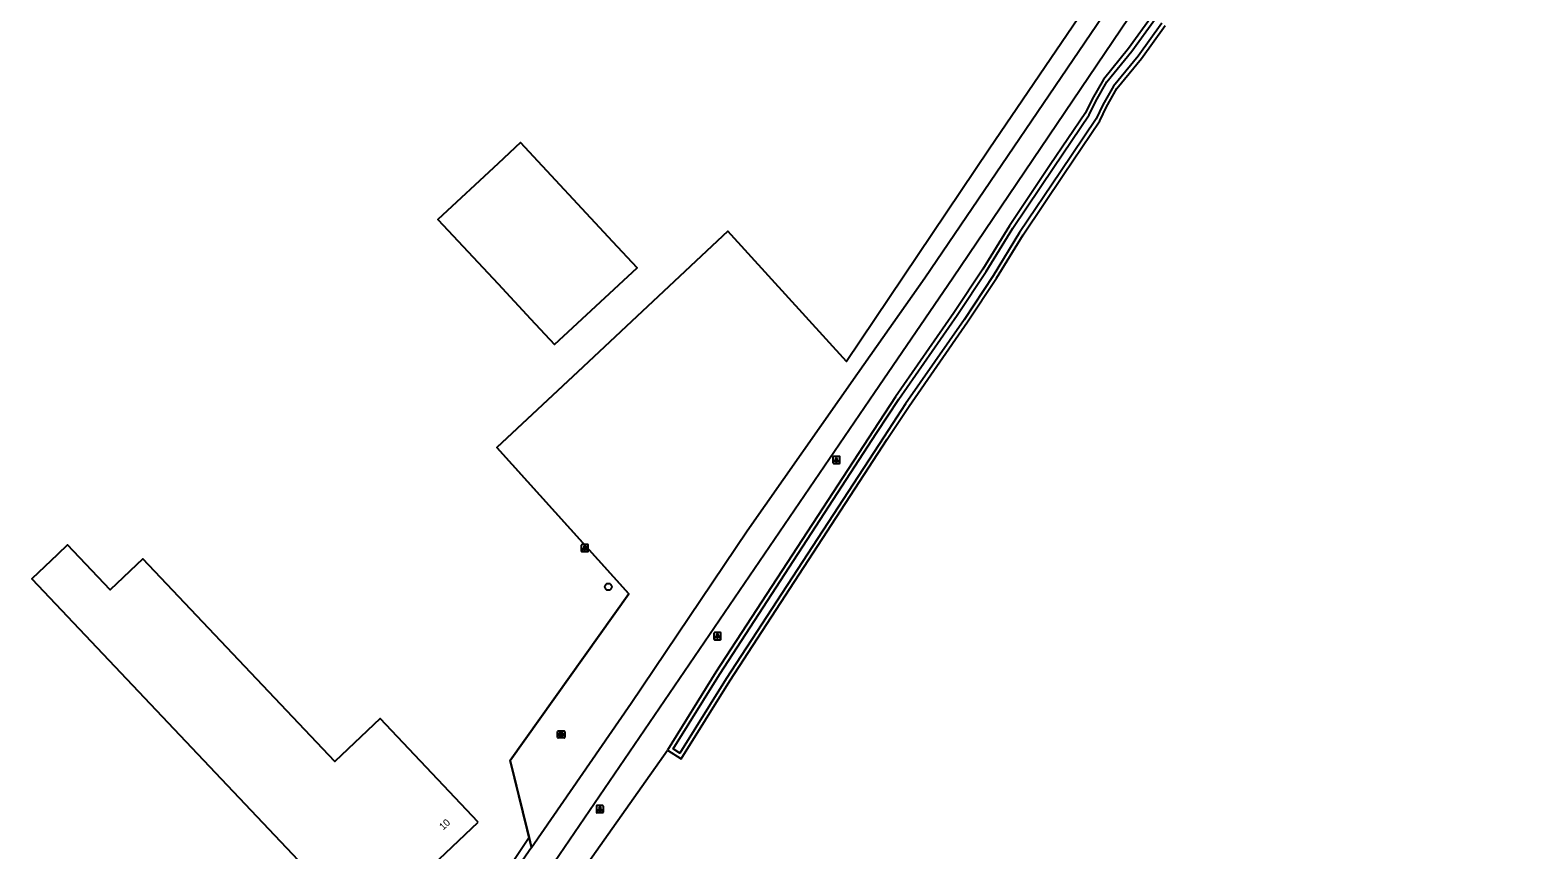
# Model space of a CAD drawing. Extents: x 158132 to 159658, y 385257 to 387209.
# Drawn here: x 158933.8 to 159147, y 385752.7 to 385868.6 of the extents above; entities that cross this region are included whole.
import ezdxf

# ---------------------------------------------------------------- set-up
doc = ezdxf.new("R2010")
doc.units = 0
for name, color, linetype in [('IMGEO_Berm_groen', 7, 'Continuous'), ('IMGEO_Boom', 7, 'Continuous'), ('IMGEO_Gemengd_bos', 7, 'Continuous'), ('IMGEO_Hek', 7, 'Continuous'), ('IMGEO_Lichtpunt', 7, 'Continuous'), ('IMGEO_Pand', 7, 'Continuous'), ('IMGEO_Pand_nummerreeks', 7, 'Continuous'), ('IMGEO_Rijbaan_lokaal_gesloten', 7, 'Continuous'), ('IMGEO_Rioolput', 7, 'Continuous'), ('IMGEO_Waterloop', 7, 'Continuous')]:
    doc.layers.add(name, color=color, linetype=linetype)

msp = doc.modelspace()

# ---------------------------------------------------------------- linework, layer by layer
at = {"layer": 'IMGEO_Berm_groen'}
for points in [[(159092.49, 385870.57), (159089.15, 385865.96), (159085.62, 385861.61), (159084.01, 385858.81), (159083.09, 385856.9), (159078.1, 385849.51), (159072.31, 385840.89), (159068.55, 385834.77), (159064.47, 385828.62), (159056.21, 385816.73), (159053.11, 385812.01), (159030.82, 385777.84), (159023.96, 385766.81)], [(159265.28, 385343.7), (159132.55, 385500.97), (159107.6, 385530.31), (159026.33, 385627.91), (159001.16, 385658.64), (158979.01, 385685.68), (158978.13, 385686.75), (158977.84, 385687.14), (158977.57, 385687.54), (158977.31, 385687.95), (158977.22, 385688.1), (158977.12, 385688.27), (158977.03, 385688.43), (158976.49, 385689.52), (158976.05, 385690.66), (158975.73, 385691.84), (158975.51, 385693.04), (158975.4, 385694.25), (158975.4, 385695.47), (158975.51, 385696.69), (158975.74, 385697.89), (158976.08, 385699.06), (158976.35, 385699.45), (159023.96, 385766.81)], [(159004.39, 385754.5), (158972.66, 385706.93)], [(159004.39, 385754.5), (159004.75, 385753.06)]]:
    msp.add_lwpolyline(points, dxfattribs=at)
at = {"layer": 'IMGEO_Boom'}
msp.add_circle((159015.6, 385789.9), 0.489, dxfattribs=at)
at = {"layer": 'IMGEO_Gemengd_bos'}
for points in [[(158893.29, 385791.82), (158915.63, 385812.94), (158887.87, 385842.1), (158903.84, 385865.93), (158906.36, 385869.7), (158907.24, 385871.01), (158908.62, 385873.86), (158932.07, 385908.86), (158950.18, 385917.14), (158998.15, 385961.05), (159000, 385959.04), (159072.96, 385880.17), (159082.08, 385870.32), (159069.43, 385851.76), (159049.28, 385821.74), (159032.5, 385840.15), (159012.02, 385820.99), (158999.83, 385809.57), (159018.49, 385788.89), (159001.72, 385765.38), (159004.39, 385754.5)], [(159023.96, 385766.81), (159025.91, 385765.6), (159032.76, 385776.6), (159055.04, 385810.75), (159058.12, 385815.44), (159066.38, 385827.33), (159070.49, 385833.53), (159074.25, 385839.64), (159080.01, 385848.22), (159085.09, 385855.75), (159086.05, 385857.73), (159087.52, 385860.3), (159090.98, 385864.55), (159094.35, 385869.21)]]:
    msp.add_lwpolyline(points, dxfattribs=at)
at = {"layer": 'IMGEO_Hek'}
for points in [[(159072.96, 385880.17), (159082.08, 385870.32), (159069.43, 385851.76)], [(159069.43, 385851.76), (159049.28, 385821.74)], [(159049.28, 385821.74), (159032.5, 385840.15), (159012.02, 385820.99)], [(159004.75, 385753.06), (159001.72, 385765.38), (159018.49, 385788.89), (158999.83, 385809.57), (159012.02, 385820.99)]]:
    msp.add_lwpolyline(points, dxfattribs=at)
at = {"layer": 'IMGEO_Lichtpunt'}
for p, q in [((159047.35, 385808.23), (159047.35, 385807.43)), ((159047.35, 385808.23), (159047.35, 385807.43)), ((159048.25, 385808.33), (159047.44, 385808.33)), ((159048.25, 385808.33), (159047.44, 385808.33)), ((159048.34, 385807.43), (159048.34, 385808.23)), ((159048.34, 385807.43), (159048.34, 385808.23)), ((159047.44, 385807.33), (159048.25, 385807.33)), ((159047.44, 385807.33), (159048.25, 385807.33)), ((159011.77, 385795.77), (159011.77, 385794.97)), ((159011.77, 385795.77), (159011.77, 385794.97)), ((159012.67, 385795.87), (159011.87, 385795.87)), ((159012.67, 385795.87), (159011.87, 385795.87)), ((159012.77, 385794.97), (159012.77, 385795.77)), ((159012.77, 385794.97), (159012.77, 385795.77)), ((159011.87, 385794.87), (159012.67, 385794.87)), ((159011.87, 385794.87), (159012.67, 385794.87)), ((159030.53, 385783.33), (159030.53, 385782.53)), ((159030.53, 385783.33), (159030.53, 385782.53)), ((159031.43, 385783.43), (159030.63, 385783.43)), ((159031.43, 385783.43), (159030.63, 385783.43)), ((159030.63, 385782.43), (159031.43, 385782.43)), ((159030.63, 385782.43), (159031.43, 385782.43)), ((159031.53, 385782.53), (159031.53, 385783.33)), ((159031.53, 385782.53), (159031.53, 385783.33)), ((159014.82, 385758.98), (159014.01, 385758.98)), ((159014.82, 385758.98), (159014.01, 385758.98)), ((159013.92, 385758.89), (159013.92, 385758.08)), ((159013.92, 385758.89), (159013.92, 385758.08)), ((159014.01, 385757.99), (159014.82, 385757.99)), ((159014.01, 385757.99), (159014.82, 385757.99)), ((159014.92, 385758.08), (159014.92, 385758.89)), ((159014.92, 385758.08), (159014.92, 385758.89))]:
    msp.add_line(p, q, dxfattribs=at)
for points in [[(159047.72, 385807.9), (159047.76, 385807.87), (159047.57, 385807.61), (159047.53, 385807.64), (159047.72, 385807.9)], [(159047.82, 385807.85), (159047.87, 385807.85), (159047.87, 385807.53), (159047.82, 385807.53), (159047.82, 385807.85)], [(159047.93, 385807.87), (159047.97, 385807.9), (159048.16, 385807.63), (159048.12, 385807.61), (159047.93, 385807.87)], [(159012.15, 385795.44), (159012.18, 385795.41), (159012, 385795.15), (159011.96, 385795.18), (159012.15, 385795.44)], [(159012.25, 385795.39), (159012.29, 385795.39), (159012.29, 385795.07), (159012.25, 385795.07), (159012.25, 385795.39)], [(159012.36, 385795.41), (159012.4, 385795.44), (159012.58, 385795.17), (159012.54, 385795.15), (159012.36, 385795.41)], [(159030.91, 385783), (159030.94, 385782.97), (159030.76, 385782.71), (159030.72, 385782.73), (159030.91, 385783)], [(159031.01, 385782.95), (159031.06, 385782.95), (159031.06, 385782.63), (159031.01, 385782.63), (159031.01, 385782.95)], [(159031.12, 385782.97), (159031.16, 385783), (159031.34, 385782.73), (159031.3, 385782.71), (159031.12, 385782.97)], [(159014.29, 385758.55), (159014.33, 385758.52), (159014.14, 385758.26), (159014.11, 385758.29), (159014.29, 385758.55)], [(159014.39, 385758.5), (159014.44, 385758.5), (159014.44, 385758.18), (159014.39, 385758.18), (159014.39, 385758.5)], [(159014.5, 385758.52), (159014.54, 385758.55), (159014.73, 385758.29), (159014.69, 385758.26), (159014.5, 385758.52)]]:
    msp.add_lwpolyline(points, dxfattribs=at)
for centre in [(159047.85, 385808.03), (159012.27, 385795.57), (159031.03, 385783.13), (159014.42, 385758.69)]:
    msp.add_circle(centre, 0.0994, dxfattribs=at)
for centre, start, end in [((159047.44, 385808.23), 90, 180), ((159047.44, 385808.23), 90, 180), ((159048.25, 385808.23), 0, 90), ((159048.25, 385808.23), 0, 90), ((159047.44, 385807.43), 180, 270), ((159047.44, 385807.43), 180, 270), ((159048.25, 385807.43), 270, 0), ((159048.25, 385807.43), 270, 360), ((159011.87, 385795.77), 90, 180), ((159011.87, 385795.77), 90, 180), ((159012.67, 385795.77), 0, 90), ((159012.67, 385795.77), 0, 90), ((159011.87, 385794.97), 180, 270), ((159011.87, 385794.97), 180, 270), ((159012.67, 385794.97), 270, 0), ((159012.67, 385794.97), 270, 360), ((159030.63, 385783.33), 90, 180), ((159030.63, 385783.33), 90, 180), ((159030.63, 385782.53), 180, 270), ((159030.63, 385782.53), 180, 270), ((159031.43, 385783.33), 0, 90), ((159031.43, 385783.33), 0, 90), ((159031.43, 385782.53), 270, 0), ((159031.43, 385782.53), 270, 360), ((159014.01, 385758.89), 90, 180), ((159014.01, 385758.89), 90, 180), ((159014.82, 385758.89), 0, 90), ((159014.82, 385758.89), 0, 90), ((159014.01, 385758.08), 180, 270), ((159014.01, 385758.08), 180, 270), ((159014.82, 385758.08), 270, 0), ((159014.82, 385758.08), 270, 360)]:
    msp.add_arc(centre, 0.0946, start, end, dxfattribs=at)
at = {"layer": 'IMGEO_Pand'}
for points in [[(159016.25, 385838.64), (159003.16, 385852.67), (159000, 385849.73), (158991.51, 385841.82), (159000, 385832.71), (159004.6, 385827.78), (159008.01, 385824.12), (159019.66, 385834.98), (159016.25, 385838.64)], [(158997.19, 385756.65), (158983.32, 385771.28), (158976.92, 385765.21), (158949.77, 385793.86), (158945.14, 385789.48), (158939.12, 385795.84), (158937.7, 385794.49), (158934.07, 385791.05), (158972.61, 385750.37), (158972.21, 385750), (158971.58, 385749.4), (158980.07, 385740.44), (158990.17, 385750), (158991.67, 385751.42), (158997.19, 385756.65)]]:
    msp.add_lwpolyline(points, dxfattribs=at)
at = {"layer": 'IMGEO_Rijbaan_lokaal_gesloten'}
for points in [[(158975.57, 385701.68), (159000, 385739.15), (159002.78, 385743.42), (159007.27, 385750), (159053.26, 385817.37), (159064.3, 385833.55), (159172.92, 385994.15)], [(159004.75, 385753.06), (159018.83, 385773.47), (159035.21, 385797.79), (159050.84, 385820.03), (159060.35, 385833.55), (159088.01, 385874.32)], [(159004.75, 385753.06), (159002.63, 385749.99), (158992.66, 385735.04), (158967.43, 385697.18)]]:
    msp.add_lwpolyline(points, dxfattribs=at)
at = {"layer": 'IMGEO_Rioolput'}
for p, q in [((159008.43, 385768.61), (159008.43, 385769.47)), ((159008.5, 385769.54), (159009.35, 385769.54)), ((159009.35, 385768.54), (159008.5, 385768.54)), ((159008.91, 385769.32), (159008.94, 385769.32)), ((159008.94, 385768.76), (159008.91, 385768.76)), ((159009.43, 385769.47), (159009.43, 385768.61))]:
    msp.add_line(p, q, dxfattribs=at)
for points in [[(159008.43, 385768.61), (159008.43, 385769.47)], [(159008.5, 385769.54), (159009.35, 385769.54)], [(159009.35, 385768.54), (159008.5, 385768.54)], [(159009.02, 385769.24), (159008.76, 385769.24), (159008.76, 385768.84)], [(159008.76, 385768.84), (159008.89, 385768.84), (159008.89, 385769), (159008.9, 385769)], [(159008.94, 385769.16), (159008.89, 385769.16), (159008.89, 385769.08)], [(159008.89, 385769.08), (159008.94, 385769.08)], [(159008.94, 385768.97), (159009.02, 385768.84), (159009.16, 385768.84), (159009.09, 385768.97)], [(159009.43, 385769.47), (159009.43, 385768.61)]]:
    msp.add_lwpolyline(points, dxfattribs=at)
for centre, radius, start, end in [((159008.5, 385769.46), 0.0765, 91.552, 178.448), ((159008.5, 385769.46), 0.0765, 91.552, 178.448), ((159008.5, 385768.62), 0.0765, 181.552, 268.448), ((159008.5, 385768.62), 0.0765, 181.552, 268.448), ((159008.9, 385768.95), 0.0533, 26.0293, 88.6989), ((159008.95, 385769.06), 0.0964, 77.0061, 93.1865), ((159008.92, 385769.27), 0.19, 274.7715, 282.9687), ((159008.96, 385769.12), 0.0378, 276.6634, 79.6772), ((159009.01, 385769.13), 0.109, 350.3612, 89.416), ((159009.01, 385769.13), 0.112, 277.5842, 350.9817), ((159009, 385768.91), 0.108, 29.5134, 73.7905), ((159009.35, 385769.46), 0.0765, 1.552, 88.448), ((159009.35, 385769.46), 0.0765, 1.552, 88.448), ((159009.35, 385768.62), 0.0765, 271.552, 358.448), ((159009.35, 385768.62), 0.0765, 271.552, 358.448)]:
    msp.add_arc(centre, radius, start, end, dxfattribs=at)
for centre, major_axis, ratio, start_param, end_param in [((159008.91, 385769.04), (-0.387, 0.002), 0.722429, 4.712389, 7.853982), ((159008.94, 385769.04), (-0.39, 0.002), 0.717154, 1.570796, 4.712389)]:
    msp.add_ellipse(centre, major_axis=major_axis, ratio=ratio, start_param=start_param, end_param=end_param, dxfattribs=at)
at = {"layer": 'IMGEO_Waterloop'}
for points in [[(159032.27, 385776.91), (159025.73, 385766.39), (159024.75, 385767), (159031.3, 385777.53), (159053.59, 385811.7), (159056.69, 385816.41), (159064.95, 385828.3), (159069.03, 385834.46), (159072.79, 385840.58), (159078.58, 385849.19), (159083.59, 385856.61), (159084.52, 385858.54), (159086.1, 385861.28), (159089.61, 385865.61), (159092.96, 385870.23)], [(159093.89, 385869.55), (159090.52, 385864.9), (159087.05, 385860.63), (159085.54, 385858), (159084.59, 385856.03), (159079.53, 385848.54), (159073.76, 385839.95), (159070.01, 385833.84), (159065.9, 385827.65), (159057.64, 385815.76), (159054.56, 385811.06), (159032.27, 385776.91)]]:
    msp.add_lwpolyline(points, dxfattribs=at)

# ---------------------------------------------------------------- texts
at = {"layer": 'IMGEO_Pand_nummerreeks'}
msp.add_text('10', height=1, rotation=43.4531, dxfattribs=at).set_placement((158992.25, 385755.45))

doc.saveas('drawing.dxf')
